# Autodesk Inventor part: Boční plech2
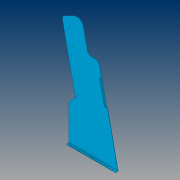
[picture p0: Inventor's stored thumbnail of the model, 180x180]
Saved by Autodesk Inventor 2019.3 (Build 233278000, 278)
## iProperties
Created: 2019-02
Part Number: Boční plech2
Material: Ocel, pozinkovaná
Document SubType Name: Plech
Designer: B-hon
Density: 7.85 g/cm^3
Sheet Metal Rule: Výchozí_mm
Appearance: Nebeská modrá – střední
Author: B-hon
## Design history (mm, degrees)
node "Plocha1"
  sketch "Náčrt1"
    geometry: L1 (0, 0)-(-244.44, 1150); L2 (314.881, 0)-(70.441, 1150); L3 (0, 0)-(314.881, 0); L4 (-244.44, 1150)-(70.441, 1150)
    constraints: 8 end point, 2 horizontal, 1 parallel
    dimensions: "d1" = 308 distance between parallel lines of L1 L2; "d2" = 1150 distance from line of L1.end L3; "d3" = 102 deg angle of L3 L1
sketch "Náčrt3"
  geometry: L1 (27.892, 860)-(-97.025, 860); L2 (-97.025, 860)-(-97.025, 480); L3 (-97.025, 480)-(27.892, 480); L4 (27.892, 480)-(27.892, 860); L5 (0, 0)-(-3, 0) reference; 1 further point
  constraints: 8 end point, 2 parallel, 1 horizontal, 1 perpendicular
  dimensions: "d10" = 480 distance between parallel lines of L5 L3; "d23" = 380 distance of L3.end L1.start
extrude "Vysunutí3" cut sketch "Náčrt3" distance "d24" = 1; taper "d25" = 0 deg
node "Obruba2"
sketch "Náčrt6"
  geometry: L1 (-13.139, 1502.331)-(147.613, 746.051); L2 (147.613, 746.051)-(295.063, 777.393); L3 (295.063, 777.393)-(134.311, 1533.672); L4 (134.311, 1533.672)-(-13.139, 1502.331); L5 (70.441, 1150)-(136.077, 841.207) reference; L6 (70.441, 1150)-(136.077, 841.207) reference; 1 further point
  constraints: 8 end point, 4 parallel, 1 perpendicular
  dimensions: "d36" = 8.5 distance between parallel lines of L1 L5
extrude "Vysunutí4" cut sketch "Náčrt6" distance "d37" = 3; taper "d38" = 0 deg
chamfer "Zkosení1" distance "d40" = 19; stored, may be unused: second distance "d41" = 2, angle "d42" = 45 deg
sketch "Náčrt7"
  geometry: L1 (-120.117, 189.338)-(203.274, 189.338); L2 (203.274, 189.338)-(203.274, -49.525); L3 (203.274, -49.525)-(-120.117, -49.525); L4 (-120.117, -49.525)-(-120.117, 189.338); L5 (-3, 94.975)-(-22, 94.975) reference; 1 further point
  constraints: 8 end point, 2 parallel, 1 horizontal, 1 perpendicular
  dimensions: "d43" = 144.5 distance between parallel lines of L5 L3
extrude "Vysunutí5" cut sketch "Náčrt7" distance "d44" = 10; taper "d45" = 0 deg
sketch "Náčrt12"
  geometry: L1 (-55.86, 1222.341)-(33.587, 801.529); L2 (33.587, 801.529)-(235.178, 844.379); L3 (235.178, 844.379)-(174.093, 1251.655); L4 (174.093, 1251.655)-(-55.86, 1222.341); L5 (157.91, 697.608)-(61.751, 1150) reference; 1 further point
  constraints: 8 end point, 1 parallel, 1 perpendicular
  dimensions: "d80" = 335 distance from line of L5.end L2; "d81" = 100 distance between parallel lines of L5 L1
extrude "Vysunutí8" cut sketch "Náčrt12" distance "d82" = 10; taper "d83" = 0 deg
sketch "Náčrt13"
  geometry: L1 (0, 0)-(-244.44, 1150) reference; L2 (0, 0)-(-155, 0); L3 (-155, 0)-(-155, 330); L4 (-155, 330)-(-87.294, 410.688)
  constraints: 6 end point, 1 horizontal, 1 perpendicular, 1 point on line
  dimensions: "d85" = 155 distance of L1.start L2.end; "d86" = 330 distance of L2.end L3.end; "d87" = 140 deg angle of L4 L3
extrude "Vysunutí10" join sketch "Náčrt13" distance "d90" = 3; taper "d91" = 0 deg
node "Obruba5"
node "Upravit přímo1"
sketch "Náčrt16"
  geometry: L1 (-244.44, 1150)-(-40.483, 1150) reference; L2 (-326.226, 950.949)-(114.869, 1175.698); L3 (114.869, 1175.698)-(98.136, 1304.653); L4 (98.136, 1304.653)-(-565.818, 1299.358); L5 (-565.818, 1299.358)-(-326.226, 950.949); L6 (-87.294, 410.688)-(-244.44, 1150) reference; 2 further points
  constraints: 8 end point, 2 point on line
  dimensions: "d128" = 27 deg angle of L2 L1; "d129" = 142 distance from line of point (-214.257, 1008) L1
extrude "Vysunutí14" cut sketch "Náčrt16" distance "d130" = 10; taper "d131" = 0 deg
fillet "Zaoblení13" dims "d132" = 64
fillet "Zaoblení14" dims "d133" = 30
fillet "Zaoblení15" dims "d134" = 48
sketch "Náčrt18"
  geometry: L1 (19, 0)-(0, 0) reference; L2 (0, 0)-(0, -215.5) reference; 2 further points
  dimensions: "d135" = 15.3 distance from line of L1 point (8.3, -15.3); "d136" = 8.3 distance from line of L2 point (8.3, -15.3)
hole "Díra1" sketch "Náčrt18" at (8.3, -15.3) diameter "d137" = 6.5; stored, may be unused: countersink angle "d141" = 90 deg, drill point angle "d143" = 118 deg; dims "d138" = 6, "d139" = 4, "d140" = 2, "d142" = 3 (= Tloušťka)
pattern_linear "Obdélníkové pole1" dims "d146" = 90
sketch "Náčrt19"
  geometry: L1 (215.083, 469.511)-(314.881, 0) reference; L2 (-149, 0)-(314.881, 0) reference; 2 further points
  dimensions: "d147" = 10 distance from line of L1 point (291.904, 60); "d148" = 60 distance from line of L2 point (291.904, 60)
hole "Díra2" sketch "Náčrt19" at (291.904, 60) diameter "d149" = 6.5; stored, may be unused: countersink angle "d153" = 90 deg, drill point angle "d155" = 118 deg; dims "d150" = 6, "d151" = 4, "d152" = 2, "d154" = 3 (= Tloušťka)
pattern_linear "Obdélníkové pole2" dims "d158" = 180
sketch "Náčrt20"
  geometry: L1 (84.45, 812.341)-(80.538, 811.509) reference; L2 (157.91, 697.608)-(141.381, 775.369) reference; L3 (-87.294, 410.688)-(-209.471, 985.483) reference; 2 further points
  dimensions: "d159" = 40 distance from line of L1 point (-123.893, 727.162); "d183" = 30 distance from line of L3 point (-123.893, 727.162)
hole "Díra3" sketch "Náčrt20" at (-123.893, 727.162) diameter "d161" = 6.5; stored, may be unused: countersink angle "d165" = 90 deg, drill point angle "d167" = 118 deg; dims "d162" = 6, "d163" = 4, "d164" = 2, "d166" = 3 (= Tloušťka)
pattern_linear "Obdélníkové pole3" dims "d170" = 150
sketch "Náčrt21"
  geometry: L1 (-104.546, 1063.9)-(-193.746, 1018.451) reference; L2 (23.607, 848.48)-(-12.889, 1020.182) reference; 2 further points
  dimensions: "d171" = 80 distance from line of point (-143.997, 954.013) L1; "d172" = 142 distance from line of L2 point (-143.997, 954.013)
hole "Díra4" sketch "Náčrt21" at (-143.997, 954.013) diameter "d173" = 6.5; stored, may be unused: countersink angle "d177" = 90 deg, drill point angle "d179" = 118 deg; dims "d174" = 6, "d175" = 4, "d176" = 2, "d178" = 3 (= Tloušťka)
pattern_linear "Obdélníkové pole4" dims "d182" = 150
node "Obruba6"
sketch "Náčrt23"
  geometry: L1 (0, 0)-(463.881, 0) reference; L2 (463.881, 20)-(463.881, 0) reference; 2 further points
  dimensions: "d194" = 10 distance from line of L1 point (428.881, 10); "d195" = 35 distance from line of L2 point (428.881, 10)
hole "Díra5" sketch "Náčrt23" at (428.881, 10) diameter "d196" = 6.4; stored, may be unused: countersink angle "d200" = 90 deg, drill point angle "d202" = 118 deg; dims "d197" = 6, "d198" = 4, "d199" = 2, "d201" = 3 (= Tloušťka)
pattern_linear "Obdélníkové pole5" dims "d205" = 197
node "Těleso1"
feature "Deska1" dims "d4" = 3 (= Tloušťka)
sketch "Náčrt5"
  geometry: L1 (379.5, 0)-(0.5, 0); L2 (0.5, 0)-(0.5, -25); L3 (0.5, -25)-(379.5, -25); L4 (379.5, -25)-(379.5, 0)
  constraints: 8 end point
feature "Deska3" dims "d4" = 3 (= Tloušťka), "d26" = 0.5, "d27" = 1.5 (= HloubkaVýštipu), "d28" = 6 (= MinimálníZbytek), "d29" = 3 (= PřechodovýPoloměr), "d30" = 25, "d31" = -90 deg, "d32" = 3 (= PoloměrOhybu), "d33" = 12 (= VelikostRohovéhoVýštipu), "d34" = 3 (= VelikostMezery), "d35" = 3 (= VelikostJacobihoPoloměru), "MezeraVystřižení" = 0.01
feature "Ohyb2" dims "d4" = 3 (= Tloušťka), "d26" = 0.5, "d27" = 1.5 (= HloubkaVýštipu), "d28" = 6 (= MinimálníZbytek), "d29" = 3 (= PřechodovýPoloměr), "d30" = 25, "d31" = -90 deg, "d32" = 3 (= PoloměrOhybu), "MezeraVystřižení" = 0.01
feature "Roh2" dims "d30" = 25, "d31" = -90 deg, "d33" = 12 (= VelikostRohovéhoVýštipu), "d34" = 3 (= VelikostMezery), "d35" = 3 (= VelikostJacobihoPoloměru)
sketch "Náčrt14"
  geometry: L1 through (165, 0) direction (-1, 0); L2 through (0, -10) direction (0, -1); L3 (0, -20)-(330, -20); L4 (330, -20)-(330, 0)
  constraints: 6 end point, 1 horizontal, 1 perpendicular, 1 vertical
feature "Deska6" dims "d4" = 3 (= Tloušťka), "d92" = 3 (= ŠířkaVýštipu), "d93" = 1.5 (= HloubkaVýštipu), "d94" = 6 (= MinimálníZbytek), "d95" = 3 (= PřechodovýPoloměr), "d96" = 20, "d97" = 90 deg, "d98" = 3 (= PoloměrOhybu), "d99" = 12 (= VelikostRohovéhoVýštipu), "d100" = 3 (= VelikostMezery), "d101" = 3 (= VelikostJacobihoPoloměru), "MezeraVystřižení" = 0.01
feature "Ohyb5" dims "d4" = 3 (= Tloušťka), "d92" = 3 (= ŠířkaVýštipu), "d93" = 1.5 (= HloubkaVýštipu), "d94" = 6 (= MinimálníZbytek), "d95" = 3 (= PřechodovýPoloměr), "d96" = 20, "d97" = 90 deg, "d98" = 3 (= PoloměrOhybu), "MezeraVystřižení" = 0.01
feature "Roh5" dims "d96" = 20, "d97" = 90 deg, "d99" = 12 (= VelikostRohovéhoVýštipu), "d100" = 3 (= VelikostMezery), "d101" = 3 (= VelikostJacobihoPoloměru)
sketch "Náčrt22"
  geometry: L1 through (-231.94, 0) direction (1, 5.08e-33); L2 through (0, 13) direction (-7.84e-33, 1); L3 (0, 26)-(-463.881, 26); L4 (-463.881, 26)-(-463.881, 0)
  constraints: 6 end point, 1 horizontal, 1 perpendicular, 1 vertical
feature "Deska7" dims "d4" = 3 (= Tloušťka), "d184" = 3 (= ŠířkaVýštipu), "d185" = 1.5 (= HloubkaVýštipu), "d186" = 6 (= MinimálníZbytek), "d187" = 3 (= PřechodovýPoloměr), "d188" = 26, "d189" = 90 deg, "d190" = 3 (= PoloměrOhybu), "d191" = 12 (= VelikostRohovéhoVýštipu), "d192" = 3 (= VelikostMezery), "d193" = 3 (= VelikostJacobihoPoloměru), "MezeraVystřižení" = 0.01
feature "Ohyb6" dims "d4" = 3 (= Tloušťka), "d184" = 3 (= ŠířkaVýštipu), "d185" = 1.5 (= HloubkaVýštipu), "d186" = 6 (= MinimálníZbytek), "d187" = 3 (= PřechodovýPoloměr), "d188" = 26, "d189" = 90 deg, "d190" = 3 (= PoloměrOhybu), "MezeraVystřižení" = 0.01
feature "Roh6" dims "d188" = 26, "d189" = 90 deg, "d191" = 12 (= VelikostRohovéhoVýštipu), "d192" = 3 (= VelikostMezery), "d193" = 3 (= VelikostJacobihoPoloměru)
feature "Posunout1" dims "d104" = -1
other parameters: "Tloušťka" = 3 (derived), "KSoučinitel" = 4.4, "PoloměrOhybu" = 3 (= Tloušťka), "ŠířkaVýštipu" = 3 (= Tloušťka), "HloubkaVýštipu" = 1.5 (= 0.5 x Tloušťka), "VelikostRohovéhoVýštipu" = 12 (= 4 x Tloušťka), "MinimálníZbytek" = 6 (= 2 x Tloušťka), "PřechodovýPoloměr" = 3 (= PoloměrOhybu), "VelikostJacobihoPoloměru" = 3 (= PoloměrOhybu), "VelikostMezery" = 3 (= Tloušťka), "d102" = 0, "d103" = 0
